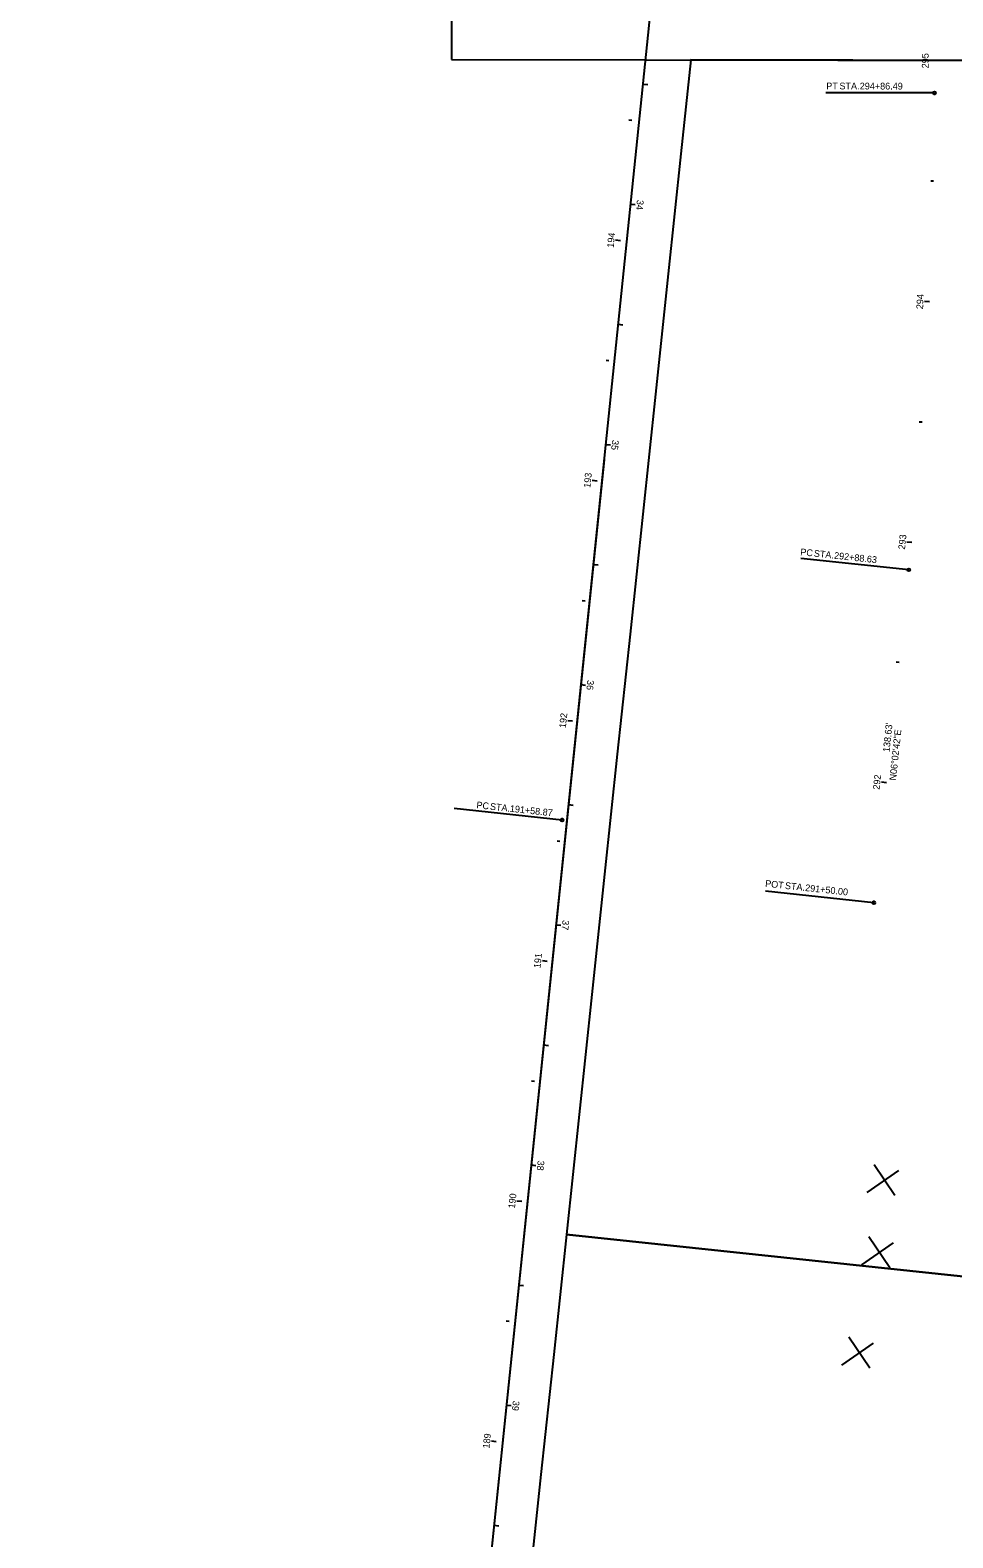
# Model space of a CAD drawing. Extents: x 172043 to 172958, y 249504 to 260295.
# Drawn here: x 172171 to 172554, y 255788 to 256412 of the extents above; entities that cross this region are included whole.
import ezdxf

# ---------------------------------------------------------------- set-up
doc = ezdxf.new("R2010")
doc.units = 0
for name, color, linetype in [('BD_X_Building', 7, 'Continuous'), ('DR_X_Storm_Sewer', 7, 'Continuous'), ('PV_X_EOP', 7, 'Continuous'), ('RS_Raster1', 7, 'Continuous'), ('RW_X_CL_100_Bearings', 7, 'Continuous'), ('RW_X_CL_100_Curve_Data', 7, 'Continuous'), ('RW_X_CL_100_Stations', 7, 'Continuous'), ('SC_Scratch1', 7, 'Continuous'), ('SV_X_Shot_Marker', 7, 'Continuous')]:
    doc.layers.add(name, color=color, linetype=linetype)

msp = doc.modelspace()

# ---------------------------------------------------------------- linework, layer by layer
at = {"layer": 'BD_X_Building'}
for p, q in [((172529.57, 255929.41), (172520.92, 255942.16)), ((172518.07, 255930.63), (172531.17, 255939.77)), ((172515.89, 255900.75), (172528.99, 255909.89)), ((172527.4, 255899.53), (172518.75, 255912.28)), ((172507.61, 255859.21), (172520.71, 255868.34)), ((172519.12, 255857.99), (172510.47, 255870.74))]:
    msp.add_line(p, q, dxfattribs=at)
at = {"layer": 'DR_X_Storm_Sewer'}
for points in [[(172345.99, 256399.91), (172745.99, 256399.15), (172746.09, 256449.15), (172746.18, 256499.15), (172746.28, 256549.15), (172746.37, 256599.15), (172746.66, 256647.48), (172747.36, 256695.73), (172748.49, 256743.97), (172750.04, 256792.2), (172752.01, 256840.45), (172754.37, 256888.9), (172354.92, 256909.87), (172352.41, 256858.44), (172350.3, 256806.77), (172348.64, 256755.05), (172347.43, 256703.32), (172346.68, 256651.58), (172346.37, 256599.91), (172346.28, 256549.91), (172346.18, 256499.91), (172346.09, 256449.91)], [(172393.52, 255913.31), (172791.29, 255871.19), (172796.56, 255920.91), (172801.83, 255970.63), (172807.09, 256020.35), (172812.36, 256070.07), (172817.62, 256119.8), (172822.89, 256169.52), (172828.15, 256219.24), (172833.42, 256268.96), (172838.68, 256318.68), (172847.18, 256398.96), (172445.03, 256399.72), (172440.91, 256360.81), (172435.64, 256311.09), (172430.38, 256261.36), (172425.11, 256211.64), (172419.85, 256161.92), (172414.58, 256112.2), (172409.32, 256062.48), (172404.05, 256012.75), (172398.78, 255963.03)], [(172320.75, 255469.43), (172697.36, 255334.65), (172714.21, 255381.73), (172731.06, 255428.8), (172754.44, 255523.13), (172759.7, 255572.85), (172764.97, 255622.58), (172770.23, 255672.3), (172775.5, 255722.02), (172780.76, 255771.74), (172786.03, 255821.46), (172791.29, 255871.19), (172393.52, 255913.31), (172388.25, 255863.59), (172382.99, 255813.87), (172377.72, 255764.14), (172372.46, 255714.42), (172367.19, 255664.7), (172361.93, 255614.98), (172356.66, 255565.26), (172354.45, 255563.58), (172337.6, 255516.51)]]:
    msp.add_lwpolyline(points, close=True, dxfattribs=at)
at = {"layer": 'PV_X_EOP'}
for p, q in [((172420.55, 256374.64), (172419.36, 256374.75)), ((172415.89, 256324.85), (172413.9, 256325.04)), ((172411.12, 256275.08), (172409.92, 256275.2)), ((172406.22, 256225.32), (172404.23, 256225.52)), ((172401.22, 256175.57), (172400.02, 256175.69)), ((172396.09, 256125.84), (172394.1, 256126.04)), ((172390.85, 256076.11), (172389.66, 256076.24)), ((172385.58, 256026.39), (172383.59, 256026.6)), ((172380.3, 255976.67), (172379.11, 255976.8)), ((172375.02, 255926.95), (172373.04, 255927.16)), ((172369.75, 255877.23), (172368.55, 255877.35)), ((172364.47, 255827.51), (172362.48, 255827.72))]:
    msp.add_line(p, q, dxfattribs=at)
at = {"layer": 'RW_X_CL_100_Bearings'}
for p, q in [((172545.97, 256386.02), (172500.97, 256386.11)), ((172535.35, 256188.54), (172490.6, 256193.28)), ((172520.75, 256050.68), (172476, 256055.41))]:
    msp.add_line(p, q, dxfattribs=at)
for centre in [(172545.97, 256386.02), (172535.35, 256188.54), (172520.75, 256050.68)]:
    msp.add_circle(centre, 0.6, dxfattribs=at)
at = {"layer": 'RW_X_CL_100_Stations'}
for p, q in [((172545.99, 256399.53), (172543.99, 256399.53)), ((172545.55, 256349.53), (172544.35, 256349.56)), ((172543.84, 256299.56), (172541.84, 256299.66)), ((172540.83, 256249.66), (172539.63, 256249.74)), ((172536.51, 256199.84), (172534.52, 256200.04)), ((172531.28, 256150.12), (172530.09, 256150.25)), ((172526.02, 256100.4), (172524.03, 256100.61)), ((172520.75, 256050.68), (172519.56, 256050.8))]:
    msp.add_line(p, q, dxfattribs=at)
at = {"layer": 'SC_Scratch1'}
for p, q in [((172428.67, 256423.35), (172177.28, 253990.91)), ((172425.19, 256389.72), (172427.18, 256389.51)), ((172420.05, 256339.98), (172422.04, 256339.78)), ((172420.05, 256339.98), (172422.04, 256339.78)), ((172414.91, 256290.25), (172416.9, 256290.04)), ((172409.77, 256240.51), (172411.76, 256240.31)), ((172409.77, 256240.51), (172411.76, 256240.31)), ((172409.1, 256234.03), (172171.47, 253934.66)), ((172404.63, 256190.78), (172406.62, 256190.57)), ((172399.49, 256141.04), (172401.48, 256140.84)), ((172399.49, 256141.04), (172401.48, 256140.84)), ((172394.35, 256091.31), (172396.34, 256091.1)), ((172389.21, 256041.57), (172391.2, 256041.37)), ((172389.21, 256041.57), (172391.2, 256041.37)), ((172384.07, 255991.84), (172386.06, 255991.63)), ((172378.93, 255942.1), (172380.92, 255941.9)), ((172378.93, 255942.1), (172380.92, 255941.9)), ((172373.79, 255892.37), (172375.78, 255892.16)), ((172368.65, 255842.63), (172370.64, 255842.43)), ((172368.65, 255842.63), (172370.64, 255842.43)), ((172363.51, 255792.9), (172365.5, 255792.69))]:
    msp.add_line(p, q, dxfattribs=at)
at = {"layer": 'SV_X_Shot_Marker'}
msp.add_line((172391.79, 256084.93), (172347.04, 256089.68), dxfattribs=at)
msp.add_circle((172391.79, 256084.93), 0.6, dxfattribs=at)

# ---------------------------------------------------------------- texts
at = {"layer": 'PV_X_EOP'}
for s, rotation, p in [('194', 84.5849, (172413.09, 256321.82)), ('193', 84.31824, (172403.42, 256222.39)), ('192', 84.05157, (172393.27, 256122.9)), ('191', 83.94188, (172382.75, 256023.45)), ('190', 83.94188, (172372.19, 255923.96)), ('189', 83.94188, (172361.64, 255824.56))]:
    msp.add_text(s, height=2.8, rotation=rotation, dxfattribs=at).set_placement(p)
at = {"layer": 'RS_Raster1'}
msp.add_text('N06°02\'42"E', height=2.8, rotation=83.95499, dxfattribs=at).set_placement((172529.99, 256101.17))
at = {"layer": 'RW_X_CL_100_Bearings'}
for s, rotation, p in [('PT', 359.89076, (172501.11, 256387.51)), (' STA. ', 359.89076, (172505.53, 256387.5)), ('294+86.49', 359.89076, (172514.98, 256387.48)), ('PC', 353.95499, (172490.27, 256194.64)), (' STA. ', 353.95499, (172494.83, 256194.15)), ('292+88.63', 353.95499, (172504.23, 256193.16)), ('POT', 353.95499, (172475.7, 256057.32)), (' STA. ', 353.95499, (172482.87, 256056.56)), ('291+50.00', 353.95499, (172492.26, 256055.56))]:
    msp.add_text(s, height=2.8, rotation=rotation, dxfattribs=at).set_placement(p)
at = {"layer": 'RW_X_CL_100_Curve_Data'}
msp.add_text("138.63'", height=2.8, rotation=83.95499, dxfattribs=at).set_placement((172527.3, 256112.97))
at = {"layer": 'RW_X_CL_100_Stations'}
for s, rotation, p in [('295', 89.89076, (172543.49, 256396.23)), ('294', 87.29597, (172541.19, 256296.41)), ('293', 84.29598, (172533.7, 256196.84)), ('292', 83.95499, (172523.18, 256097.4))]:
    msp.add_text(s, height=2.8, rotation=rotation, dxfattribs=at).set_placement(p)
at = {"layer": 'SC_Scratch1'}
for s, p in [('34', (172422.76, 256341.87)), ('35', (172412.48, 256242.43)), ('36', (172402.21, 256143.02)), ('37', (172391.93, 256043.6)), ('38', (172381.65, 255944.05)), ('39', (172371.36, 255844.57))]:
    msp.add_text(s, height=2.8, rotation=264.09958, dxfattribs=at).set_placement(p)
at = {"layer": 'SV_X_Shot_Marker'}
for s, p in [('PC', (172356.15, 256089.84)), (' STA. ', (172360.72, 256089.35)), ('191+58.87', (172369.99, 256088.37))]:
    msp.add_text(s, height=2.8, rotation=353.94188, dxfattribs=at).set_placement(p)

doc.saveas('drawing.dxf')
